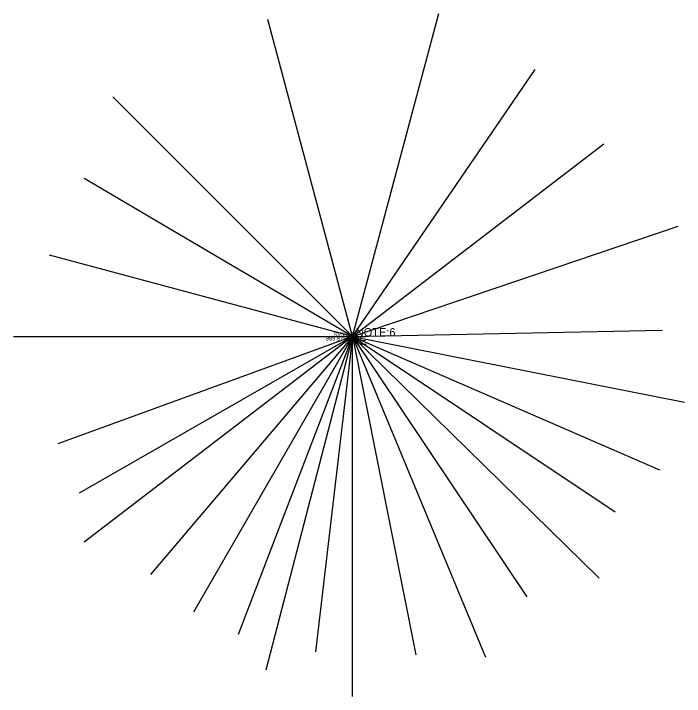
# Model space of a CAD drawing. Extents: x 179577 to 181071, y 300448 to 300709.
# Drawn here: x 179647.77 to 179657.53, y 300631.25 to 300641.18 of the extents above; entities that cross this region are included whole.
import ezdxf

# ---------------------------------------------------------------- set-up
doc = ezdxf.new("R2010")
doc.units = 0
for name, color, linetype in [('RD_X_Cells', 7, 'Continuous'), ('SV_X_Shot_Marker', 7, 'Continuous'), ('SV_X_Text_Comment', 7, 'Continuous'), ('SV_X_Text_Name', 7, 'Continuous'), ('UT_X_Misc_Cells', 7, 'Continuous')]:
    doc.layers.add(name, color=color, linetype=linetype)

msp = doc.modelspace()

# ---------------------------------------------------------------- linework, layer by layer
at = {"layer": 'RD_X_Cells'}
for p, q in [((179652.7054, 300636.4866), (179653.9621, 300641.1849)), ((179652.7054, 300636.4866), (179651.4704, 300641.0999)), ((179652.7054, 300636.4866), (179655.3604, 300640.3716)), ((179652.7054, 300636.4866), (179649.2154, 300639.9733)), ((179652.7054, 300636.4866), (179656.3621, 300639.2916)), ((179652.7054, 300636.4866), (179648.7987, 300638.7833)), ((179652.7054, 300636.4866), (179657.4421, 300638.0933)), ((179652.7054, 300636.4866), (179648.2921, 300637.6699)), ((179652.7054, 300636.4866), (179657.2154, 300636.5783)), ((179647.7704, 300636.4866), (179652.7054, 300636.4866)), ((179652.7054, 300636.4866), (179648.4154, 300634.9249)), ((179652.7054, 300636.4866), (179648.7221, 300634.2049)), ((179652.7054, 300636.4866), (179648.7987, 300633.4916)), ((179652.7054, 300636.4866), (179649.7604, 300633.0199)), ((179652.7054, 300636.4866), (179650.3871, 300632.4716)), ((179652.7054, 300636.4866), (179651.0404, 300632.1466)), ((179652.7054, 300636.4866), (179651.4421, 300631.6299)), ((179652.7054, 300636.4866), (179652.1637, 300631.8949)), ((179652.7054, 300631.2466), (179652.7054, 300636.4866)), ((179652.7054, 300636.4866), (179653.6271, 300631.8499)), ((179652.7054, 300636.4866), (179654.6387, 300631.8183)), ((179652.7054, 300636.4866), (179655.2421, 300632.6933)), ((179652.7054, 300636.4866), (179656.2937, 300632.9649)), ((179652.7054, 300636.4866), (179656.5271, 300633.9316)), ((179652.7054, 300636.4866), (179657.1704, 300634.5449)), ((179652.7054, 300636.4866), (179657.5337, 300635.5283))]:
    msp.add_line(p, q, dxfattribs=at)

# ---------------------------------------------------------------- texts
at = {"layer": 'SV_X_Shot_Marker'}
msp.add_text('SV5014', height=0.06, dxfattribs=at).set_placement((179652.4262, 300636.4866))
at = {"layer": 'SV_X_Text_Comment'}
msp.add_text('889.8750', height=0.06, dxfattribs=at).set_placement((179652.3152, 300636.4266))
at = {"layer": 'SV_X_Text_Name'}
msp.add_text('TE', height=0.12, dxfattribs=at).set_placement((179652.7054, 300636.3666))
at = {"layer": 'UT_X_Misc_Cells'}
msp.add_text(' NOTE:6', height=0.12, dxfattribs=at).set_placement((179652.7054, 300636.4866))

doc.saveas('drawing.dxf')
